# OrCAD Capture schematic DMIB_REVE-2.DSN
size Custom; title: dMIB_RevE; rev: E; company: Intuitive Surgical, Inc.; note: TBD; note: 1266 Kifer Road; note: Sunnyvale, CA 94086
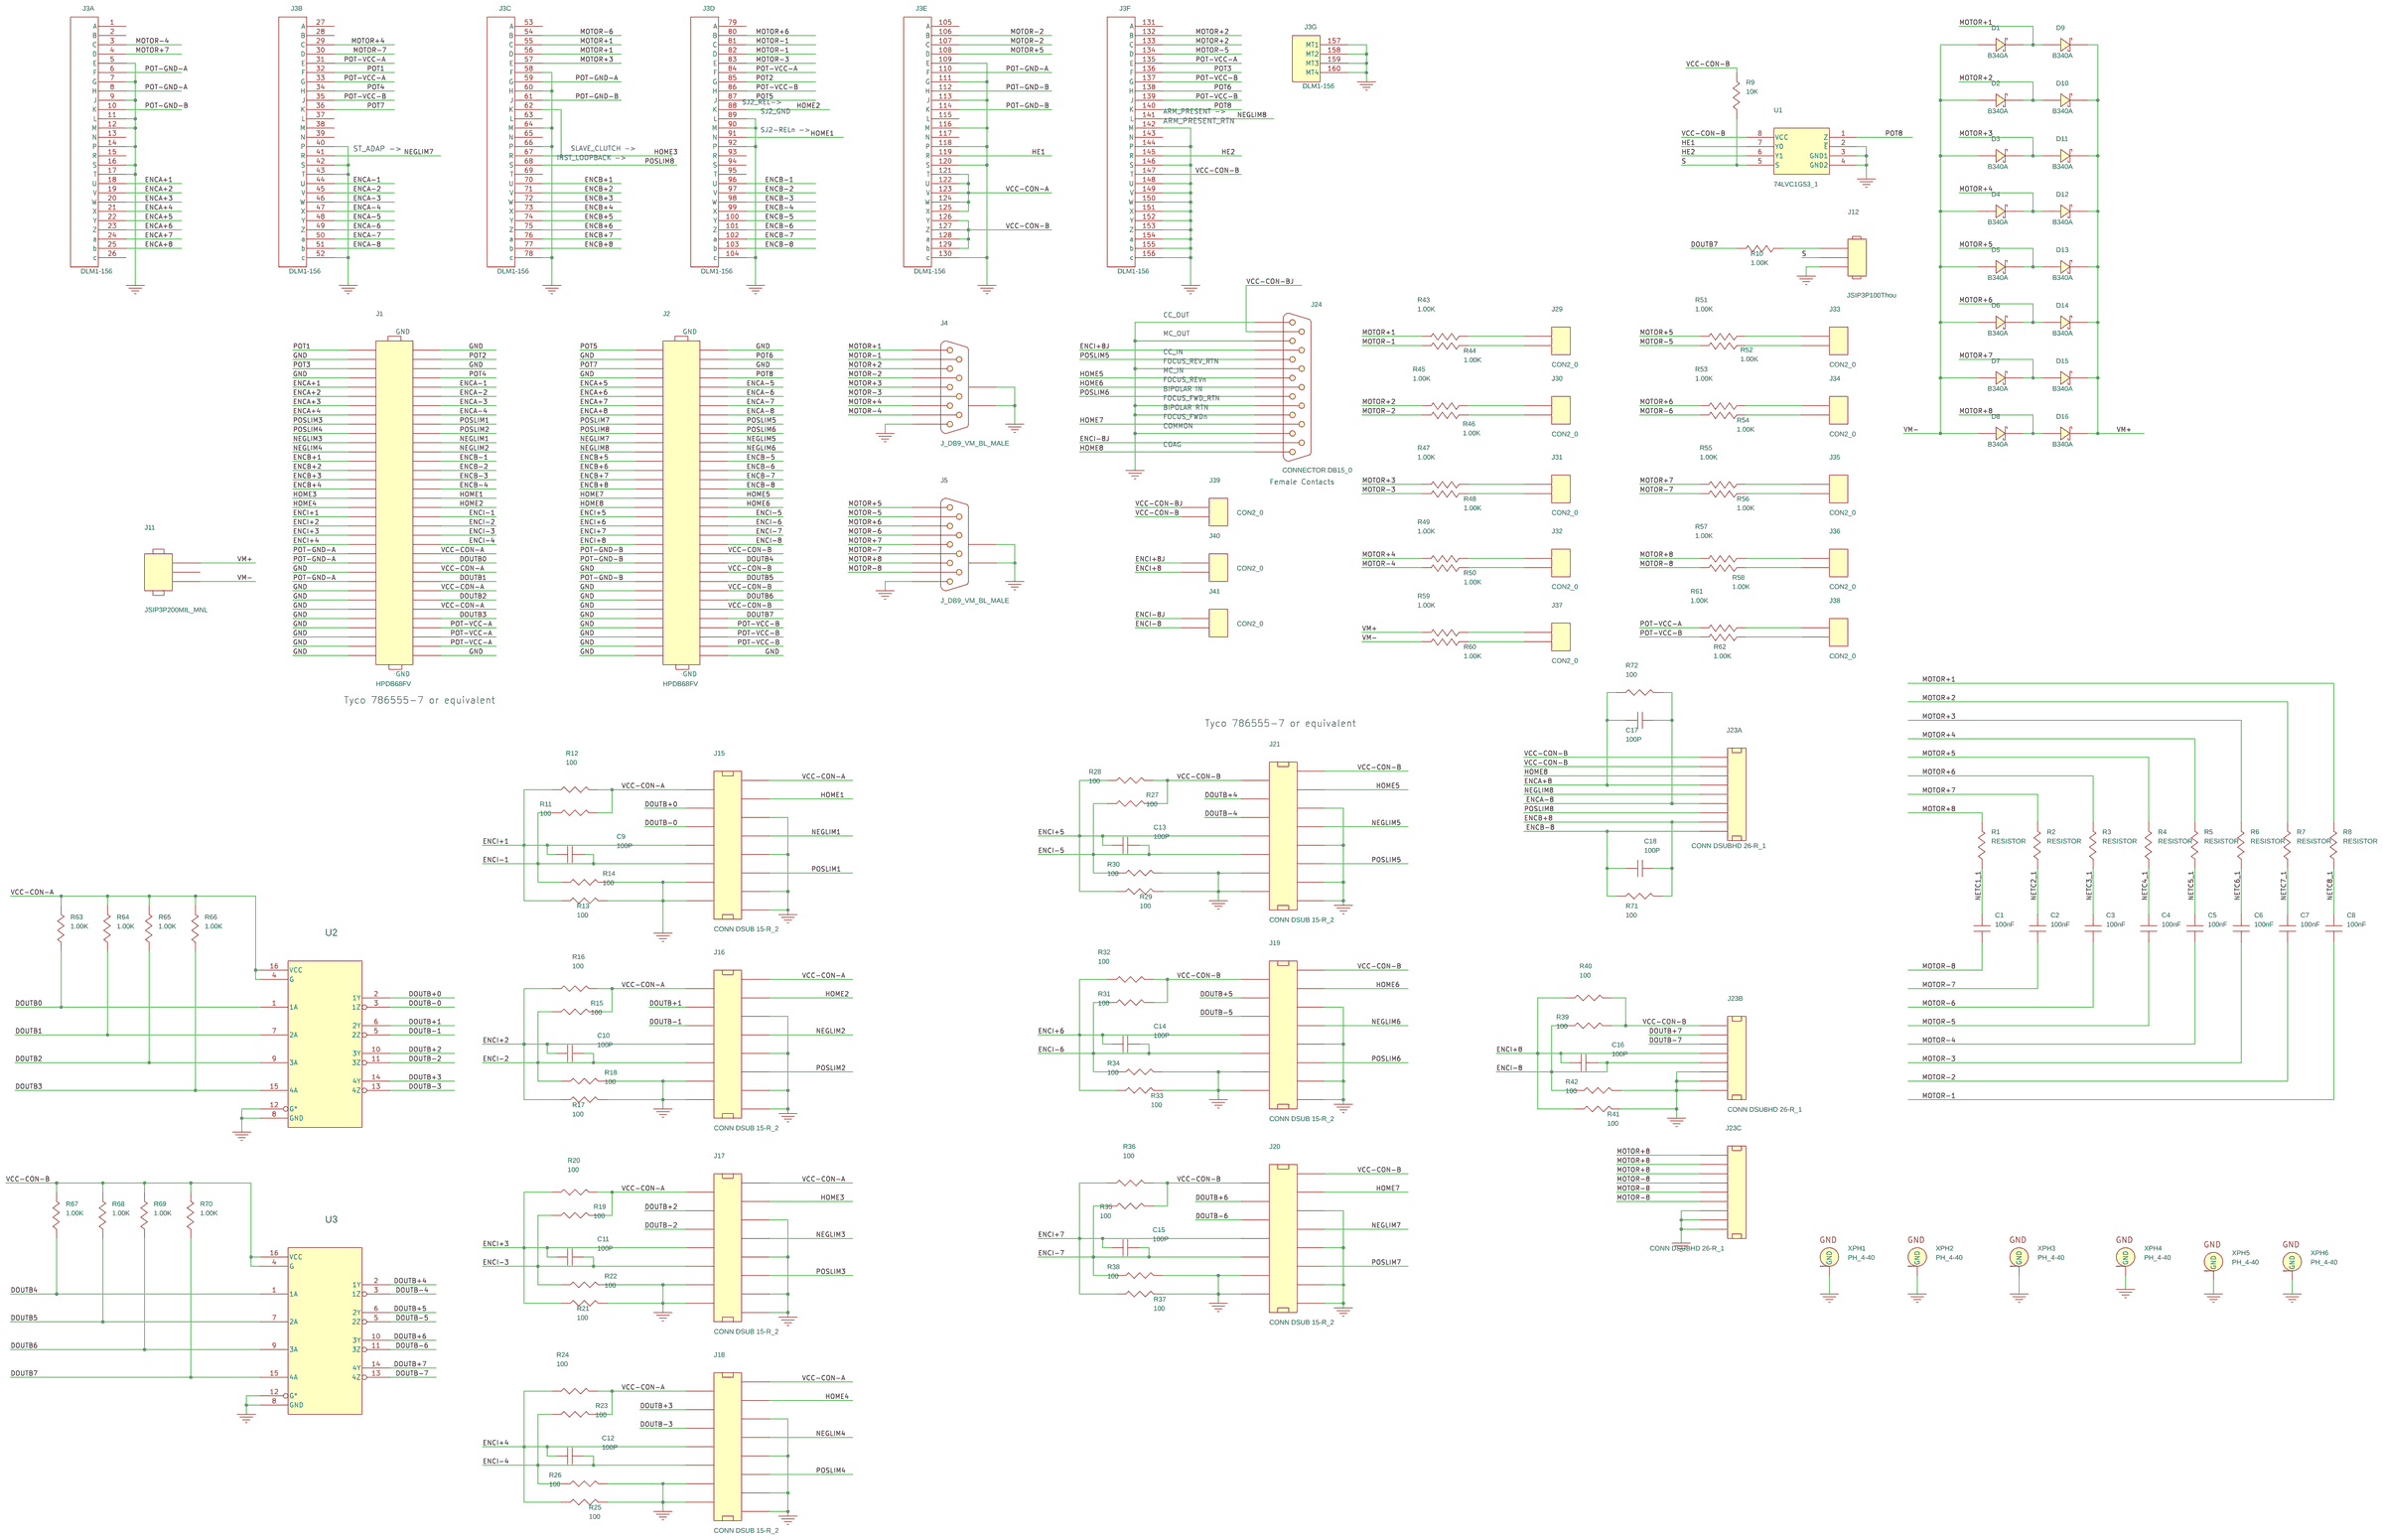
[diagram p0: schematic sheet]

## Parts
C1  100nF  [C1206]
C2  100nF  [C0805]
C3  100nF  [C0805]
C4  100nF  [C0805]
C5  100nF  [C0805]
C6  100nF  [C0805]
C7  100nF  [C0805]
C8  100nF  [C0805]
C9  100P  [C0402]
C10  100P  [C0402]
C11  100P  [C0402]
C12  100P  [C0402]
C13  100P  [C0402]
C14  100P  [C0402]
C15  100P  [C0402]
C16  100P  [C0402]
C17  100P  [C0402]
C18  100P  [C0402]
D1  B340A  [SMA]
D2  B340A  [SMA]
D3  B340A  [SMA]
D4  B340A  [SMA]
D5  B340A  [SMA]
D6  B340A  [SMA]
D7  B340A  [SMA]
D8  B340A  [SMA]
D9  B340A  [SMA]
D10  B340A  [SMA]
D11  B340A  [SMA]
D12  B340A  [SMA]
D13  B340A  [SMA]
D14  B340A  [SMA]
D15  B340A  [SMA]
D16  B340A  [SMA]
J1  HPDB68FV  [HPDB68FV]
J2  HPDB68FV  [HPDB68FV]
J3  DLM1-156  [DLM1-156]  (sections A,B,C,D,E,F,G)
J4  J_DB9_VM_BL_MALE  [DB9M]
J5  J_DB9_VM_BL_MALE  [DB9M]
J11  JSIP3P200MIL_MNL  [TB-3/5.08]
J12  JSIP3P100Thou  [JSIP3P2.54MM]
J15  CONN DSUB 15-R_2  [DSUBHD/VP/TF/15]
J16  CONN DSUB 15-R_2  [DSUBHD/VP/TM/OS/15]
J17  CONN DSUB 15-R_2  [DSUBHD/VP/TF/15]
J18  CONN DSUB 15-R_2  [DSUBHD/VP/TF/15]
J19  CONN DSUB 15-R_2  [DSUBHD/VP/TF/15]
J20  CONN DSUB 15-R_2  [DSUBHD/VP/TF/15]
J21  CONN DSUB 15-R_2  [DSUBHD/VP/TF/15]
J23  CONN DSUBHD 26-R_1  [DSUBHD/VP/TF/26]  (sections A,B,C)
J24  CONNECTOR DB15_0  [DSUB/VP/TM/15]
J29  CON2_0  [JSIP2P2.54MM]
J30  CON2_0  [JSIP2P2.54MM]
J31  CON2_0  [JSIP2P2.54MM]
J32  CON2_0  [JSIP2P2.54MM]
J33  CON2_0  [JSIP2P2.54MM]
J34  CON2_0  [JSIP2P2.54MM]
J35  CON2_0  [JSIP2P2.54MM]
J36  CON2_0  [JSIP2P2.54MM]
J37  CON2_0  [JSIP2P2.54MM]
J38  CON2_0  [JSIP2P2.54MM]
J39  CON2_0  [JSIP2P2.54MM]
J40  CON2_0  [JSIP2P2.54MM]
J41  CON2_0  [JSIP2P2.54MM]
R1  RESISTOR
R2  RESISTOR
R3  RESISTOR
R4  RESISTOR
R5  RESISTOR
R6  RESISTOR
R7  RESISTOR
R8  RESISTOR
R9  10K  [r0402]
R10  1.00K  [r0402]
R11  100  [r0603]
R12  100  [r0603]
R13  100  [r0603]
R14  100  [r0603]
R15  100  [r0603]
R16  100  [r0603]
R17  100  [r0603]
R18  100  [r0603]
R19  100  [r0603]
R20  100  [r0603]
R21  100  [r0603]
R22  100  [r0603]
R23  100  [r0603]
R24  100  [r0603]
R25  100  [r0603]
R26  100  [r0603]
R27  100  [r0603]
R28  100  [r0603]
R29  100  [r0603]
R30  100  [r0603]
R31  100  [r0603]
R32  100  [r0603]
R33  100  [r0603]
R34  100  [r0603]
R35  100  [r0603]
R36  100  [r0603]
R37  100  [r0603]
R38  100  [r0603]
R39  100  [r0603]
R40  100  [r0603]
R41  100  [r0603]
R42  100  [r0603]
R43  1.00K  [r0402]
R44  1.00K  [r0402]
R45  1.00K  [r0402]
R46  1.00K  [r0402]
R47  1.00K  [r0402]
R48  1.00K  [r0402]
R49  1.00K  [r0402]
R50  1.00K  [r0402]
R51  1.00K  [r0402]
R52  1.00K  [r0402]
R53  1.00K  [r0402]
R54  1.00K  [r0402]
R55  1.00K  [r0402]
R56  1.00K  [r0402]
R57  1.00K  [r0402]
R58  1.00K  [r0402]
R59  1.00K  [r0402]
R60  1.00K  [r0402]
R61  1.00K  [r0402]
R62  1.00K  [r0402]
R63  1.00K  [r0402]
R64  1.00K  [r0402]
R65  1.00K  [r0402]
R66  1.00K  [r0402]
R67  1.00K  [r0402]
R68  1.00K  [r0402]
R69  1.00K  [r0402]
R70  1.00K  [r0402]
R71  100  [r0603]
R72  100  [r0603]
U1  74LVC1G53_1  [TSSOP8]
U2  Uam26c31ipwTssop16_1  [TSSOP16]
U3  Uam26c31ipwTssop16_1  [TSSOP16]
XPH1  PH_4-40  [mtg120p]
XPH2  PH_4-40  [mtg120p]
XPH3  PH_4-40  [mtg120p]
XPH4  PH_4-40  [mtg120p]
XPH5  PH_4-40  [mtg120p]
XPH6  PH_4-40  [mtg120p]

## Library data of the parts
C1-C8 = 177013_100N_X7R_100V_10%_0
C9-C18 = C_100pF_5%_50V_NPO_0402
D1-D16 = 173224_DIODE_B340A_SCH_40V_2.0A
J1 J2 = HPDB68FV_0
J3 = DLM1-156
J4 J5 = J_DB9_VM_BL_MALE
J11 = JSIP3P200MIL_MNL
J12 = JSIP3P100Thou
J15-J21 = CONN_DSUB_15-R_2
J23 = CONN_DSUBHD_26-R_1
J24 = CONNECTOR_DB15_1
J29-J41 = CON2_0
R1-R8 = RESISTOR
R9 = R_10K_1%_TF_0402
R10 R43-R70 = 179600_1.00K_1_16W_0402
R11-R42 R71 R72 = 143512_100_0603
U1 = 74LVC1G53_1
U2 U3 = Uam26c31ipwTssop16_1
XPH1-XPH6 = 135006_GND_Plated_Hole_120_mil

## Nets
GND: J1.1 J1.3 J1.34 J1.36 J1.38 J1.59 J1.61 J1.62 J1.63 J1.64 J1.65 J1.66 J1.67 J1.68 J1.69(GND) J1.70(GND) J2.1 J2.3 J2.34 J2.36 J2.38 J2.59 J2.61 J2.62 J2.63 J2.64 J2.65 J2.66 J2.67 J2.68 J2.69(GND) J2.70(GND) J3.5(E) J3.7(G) J3.9(J) J3.11(L) J3.12(M) J3.14(P) J3.16(S) J3.17(T) J3.40(P) J3.42(S) J3.43(T) J3.52(c) J3.58(F) J3.60(H) J3.64(M) J3.66(P) J3.78(c) J3.89(L) J3.90(M) J3.92(P) J3.104(c) J3.109(E) J3.111(G) J3.113(J) J3.116(M) J3.118(P) J3.120(S) J3.130(c) J3.142(M) J3.144(P) J3.146(S) J3.148(U) J3.149(V) J3.150(W) J3.151(X) J3.152(Y) J3.153(Z) J3.154(a) J3.155(b) J3.156(c) J3.157(MT1) J3.158(MT2) J3.159(MT3) J3.160(MT4) J4.5 J4.10 J4.11 J5.5 J5.10 J5.11 J12.3 J15.1 J15.2 J15.4 J15.6 J15.9 J15.10 J16.1 J16.2 J16.4 J16.6 J16.9 J16.10 J17.1 J17.2 J17.4 J17.6 J17.9 J17.10 J18.1 J18.2 J18.4 J18.6 J18.9 J18.10 J19.1 J19.2 J19.4 J19.6 J19.9 J19.10 J20.1 J20.2 J20.4 J20.6 J20.9 J20.10 J21.1 J21.2 J21.4 J21.6 J21.9 J21.10 J23.10 J23.11 J23.12 J23.18 J23.19 J23.20 J24.2 J24.3 J24.7 J24.8 J24.11 J24.13 R13.2 R14.2 R17.2 R18.2 R21.2 R22.2 R25.2 R26.2 R29.2 R30.2 R33.2 R34.2 R37.2 R38.2 R41.2 R42.2 U1.2(~{E}) U1.3(GND1) U1.4(GND2) U2.8(GND) U2.12(G*) U3.8(GND) U3.12(G*) XPH1.1(GND) XPH2.1(GND) XPH3.1(GND) XPH4.1(GND) XPH5.1(GND) XPH6.1(GND)
VCC-CON-A: J1.23 J1.25 J1.27 J1.29 J3.121(T) J3.122(U) J3.123(V) J3.124(W) J3.125(X) J15.8 J15.15 J16.8 J16.15 J17.8 J17.15 J18.8 J18.15 R11.2 R12.2 R15.2 R16.2 R19.2 R20.2 R23.2 R24.2 R63.1 R64.1 R65.1 R66.1 U2.4(G) U2.16(VCC)
VCC-CON-B: J2.23 J2.25 J2.27 J2.29 J3.126(Y) J3.127(Z) J3.128(a) J3.129(b) J3.147(T) J19.8 J19.15 J20.8 J20.15 J21.8 J21.15 J23.8 J23.9 J23.17 J39.2 R9.1 R27.2 R28.2 R31.2 R32.2 R35.2 R36.2 R39.2 R40.2 R67.1 R68.1 R69.1 R70.1 U1.8(VCC) U3.4(G) U3.16(VCC)
VCC-CON-BJ: J24.15 J39.1
DOUTB0: J1.24 R63.2 U2.1(1A)
DOUTB1: J1.26 R64.2 U2.7(2A)
DOUTB2: J1.28 R65.2 U2.9(3A)
DOUTB3: J1.30 R66.2 U2.15(4A)
DOUTB4: J2.24 R67.2 U3.1(1A)
DOUTB5: J2.26 R68.2 U3.7(2A)
DOUTB6: J2.28 R69.2 U3.9(3A)
DOUTB7: J2.30 R10.1 R70.2 U3.15(4A)
DOUTB+0: J15.14 U2.2(1Y)
DOUTB+1: J16.14 U2.6(2Y)
DOUTB+2: J17.14 U2.10(3Y)
DOUTB+3: J18.14 U2.14(4Y)
DOUTB+4: J21.14 U3.2(1Y)
DOUTB+5: J19.14 U3.6(2Y)
DOUTB+6: J20.14 U3.10(3Y)
DOUTB+7: J23.16 U3.14(4Y)
DOUTB-0: J15.13 U2.3(1Z)
DOUTB-1: J16.13 U2.5(2Z)
DOUTB-2: J17.13 U2.11(3Z)
DOUTB-3: J18.13 U2.13(4Z)
DOUTB-4: J21.13 U3.3(1Z)
DOUTB-5: J19.13 U3.5(2Z)
DOUTB-6: J20.13 U3.11(3Z)
DOUTB-7: J23.15 U3.13(4Z)
ENCA+1: J1.39 J3.18(U)
ENCA+2: J1.40 J3.19(V)
ENCA+3: J1.41 J3.20(W)
ENCA+4: J1.42 J3.21(X)
ENCA+5: J2.39 J3.22(Y)
ENCA+6: J2.40 J3.23(Z)
ENCA+7: J2.41 J3.24(a)
ENCA+8: C17.2 J2.42 J3.25(b) J23.6 R72.1
ENCA-1: J1.5 J3.44(U)
ENCA-2: J1.6 J3.45(V)
ENCA-3: J1.7 J3.46(W)
ENCA-4: J1.8 J3.47(X)
ENCA-5: J2.5 J3.48(Y)
ENCA-6: J2.6 J3.49(Z)
ENCA-7: J2.7 J3.50(a)
ENCA-8: C17.1 J2.8 J3.51(b) J23.4 R72.2
ENCB+1: J1.47 J3.70(U)
ENCB+2: J1.48 J3.71(V)
ENCB+3: J1.49 J3.72(W)
ENCB+4: J1.50 J3.73(X)
ENCB+5: J2.47 J3.74(Y)
ENCB+6: J2.48 J3.75(Z)
ENCB+7: J2.49 J3.76(a)
ENCB+8: C18.1 J2.50 J3.77(b) J23.2 R71.2
ENCB-1: J1.13 J3.96(U)
ENCB-2: J1.14 J3.97(V)
ENCB-3: J1.15 J3.98(W)
ENCB-4: J1.16 J3.99(X)
ENCB-5: J2.13 J3.100(Y)
ENCB-6: J2.14 J3.101(Z)
ENCB-7: J2.15 J3.102(a)
ENCB-8: C18.2 J2.16 J3.103(b) J23.1 R71.1
ENCI+1: C9.1 J1.53 J15.12 R12.1 R13.1
ENCI+2: C10.1 J1.54 J16.12 R16.1 R17.1
ENCI+3: C11.1 J1.55 J17.12 R20.1 R21.1
ENCI+4: C12.1 J1.56 J18.12 R24.1 R25.1
ENCI+5: C13.1 J2.53 J21.12 R28.1 R29.1
ENCI+6: C14.1 J2.54 J19.12 R32.1 R33.1
ENCI+7: C15.1 J2.55 J20.12 R36.1 R37.1
ENCI+8: C16.1 J2.56 J23.14 J40.2 R40.1 R41.1
ENCI+8J: J24.14 J40.1
ENCI-1: C9.2 J1.19 J15.11 R11.1 R14.1
ENCI-2: C10.2 J1.20 J16.11 R15.1 R18.1
ENCI-3: C11.2 J1.21 J17.11 R19.1 R22.1
ENCI-4: C12.2 J1.22 J18.11 R23.1 R26.1
ENCI-5: C13.2 J2.19 J21.11 R27.1 R30.1
ENCI-6: C14.2 J2.20 J19.11 R31.1 R34.1
ENCI-7: C15.2 J2.21 J20.11 R35.1 R38.1
ENCI-8: C16.2 J2.22 J23.13 J41.2 R39.1 R42.1
ENCI-8J: J24.9 J41.1
HE1: J3.119(R) U1.7(Y0)
HE2: J3.145(R) U1.6(Y1)
HOME1: J1.17 J3.91(N) J15.7
HOME2: J1.18 J3.88(K) J16.7
HOME3: J1.51 J3.62(K) J3.67(R) J17.7
HOME4: J1.52 J18.7
HOME5: J2.17 J21.7 J24.5
HOME6: J2.18 J19.7 J24.12
HOME7: J2.51 J20.7 J24.10
HOME8: J2.52 J23.7 J24.1
MOTOR+1: D1.1(CATHODE) D9.2(ANODE) J3.55(C) J3.56(D) J4.1 R8.1 R43.1
MOTOR+2: D2.1(CATHODE) D10.2(ANODE) J3.132(B) J3.133(C) J4.2 R7.1 R45.1
MOTOR+3: D3.1(CATHODE) D11.2(ANODE) J3.57(E) J4.3 R6.1 R47.1
MOTOR+4: D4.1(CATHODE) D12.2(ANODE) J3.29(C) J4.4 R5.1 R49.1
MOTOR+5: D5.1(CATHODE) D13.2(ANODE) J3.108(D) J5.1 R4.1 R51.1
MOTOR+6: D6.1(CATHODE) D14.2(ANODE) J3.80(B) J5.2 R3.1 R53.1
MOTOR+7: D7.1(CATHODE) D15.2(ANODE) J3.4(D) J5.3 R2.1 R55.1
MOTOR+8: D8.1(CATHODE) D16.2(ANODE) J5.4 J23.24 J23.25 J23.26 R1.1 R57.1
MOTOR-1: C8.2 J3.81(C) J3.82(D) J4.6 R44.1
MOTOR-2: C7.2 J3.106(B) J3.107(C) J4.7 R46.1
MOTOR-3: C6.2 J3.83(E) J4.8 R48.1
MOTOR-4: C5.2 J3.3(C) J4.9 R50.1
MOTOR-5: C4.2 J3.134(D) J5.6 R52.1
MOTOR-6: C3.2 J3.54(B) J5.7 R54.1
MOTOR-7: C2.2 J3.30(D) J5.8 R56.1
MOTOR-8: C1.2 J5.9 J23.21 J23.22 J23.23 R58.1
NEGLIM1: J1.11 J15.5
NEGLIM2: J1.12 J16.5
NEGLIM3: J1.45 J17.5
NEGLIM4: J1.46 J18.5
NEGLIM5: J2.11 J21.5
NEGLIM6: J2.12 J19.5
NEGLIM7: J2.45 J3.41(R) J20.5
NEGLIM8: J2.46 J3.141(L) J23.5
NETC1_1: C1.1 R1.2
NETC2_1: C2.1 R2.2
NETC3_1: C3.1 R3.2
NETC4_1: C4.1 R4.2
NETC5_1: C5.1 R5.2
NETC6_1: C6.1 R6.2
NETC7_1: C7.1 R7.2
NETC8_1: C8.1 R8.2
POSLIM1: J1.9 J15.3
POSLIM2: J1.10 J16.3
POSLIM3: J1.43 J17.3
POSLIM4: J1.44 J18.3
POSLIM5: J2.9 J21.3 J24.6
POSLIM6: J2.10 J19.3 J24.4
POSLIM7: J2.43 J20.3
POSLIM8: J2.44 J3.68(S) J23.3
POT1: J1.35 J3.32(F)
POT2: J1.2 J3.85(G)
POT3: J1.37 J3.136(F)
POT4: J1.4 J3.34(H)
POT5: J2.35 J3.87(J)
POT6: J2.2 J3.138(H)
POT7: J2.37 J3.36(K)
POT8: J2.4 J3.140(K) U1.1(Z)
POT-GND-A: J1.57 J1.58 J1.60 J3.6(F) J3.8(H) J3.59(G) J3.110(F)
POT-GND-B: J2.57 J2.58 J2.60 J3.10(K) J3.61(J) J3.112(H) J3.114(K)
POT-VCC-A: J1.31 J1.32 J1.33 J3.31(E) J3.33(G) J3.84(F) J3.135(E) R61.1
POT-VCC-B: J2.31 J2.32 J2.33 J3.35(J) J3.86(H) J3.137(G) J3.139(J) R62.1
S: J12.2 R9.2 U1.5(S)
VM+: D9.1(CATHODE) D10.1(CATHODE) D11.1(CATHODE) D12.1(CATHODE) D13.1(CATHODE) D14.1(CATHODE) D15.1(CATHODE) D16.1(CATHODE) J11.3 R59.1
VM-: D1.2(ANODE) D2.2(ANODE) D3.2(ANODE) D4.2(ANODE) D5.2(ANODE) D6.2(ANODE) D7.2(ANODE) D8.2(ANODE) J11.1 R60.1
N582392: J12.1 R10.2
N1339487: J29.1 R43.2
N1340524: J29.2 R44.2
N1344904: J30.1 R45.2
N1344908: J30.2 R46.2
N1346083: J31.1 R47.2
N1346087: J31.2 R48.2
N1347270: J32.1 R49.2
N1347274: J32.2 R50.2
N1348465: J33.1 R51.2
N1348469: J33.2 R52.2
N1349668: J34.1 R53.2
N1349672: J34.2 R54.2
N1350879: J35.1 R55.2
N1350883: J35.2 R56.2
N1352098: J36.1 R57.2
N1352102: J36.2 R58.2
N1373387: J37.1 R59.2
N1373391: J37.2 R60.2
N1376622: J38.1 R61.2
N1376626: J38.2 R62.2

Not connected (* = marked no-connect by the designer): J3 1(A) 2(B) 13(N) 15(R) 26(c) 27(A) 28(B) 37(L) 38(M) 39(N) 53(A) 63(L) 65(N) 69(T) 79(A) 93(R) 94(S) 95(T) 105(A) 115(L) 117(N) 131(A) 143(N); J11 2

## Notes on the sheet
- SJ2_REL->
- SJ2_GND
- ARM_PRESENT ->
- ARM_PRESENT_RTN
- SJ2-RELn ->
- ST_ADAP ->
- SLAVE_CLUTCH ->
- INST_LOOPBACK ->
- CC_OUT
- MC_OUT
- CC_IN
- FOCUS_REV_RTN
- MC_IN
- FOCUS_REVn
- BIPOLAR IN
- BIPOLAR RTN
- FOCUS_FWD_RTN
- FOCUS_FWDn
- COMMON
- COAG
- Female Contacts
- Tyco 786555-7 or equivalent
- Tyco 786555-7 or equivalent
